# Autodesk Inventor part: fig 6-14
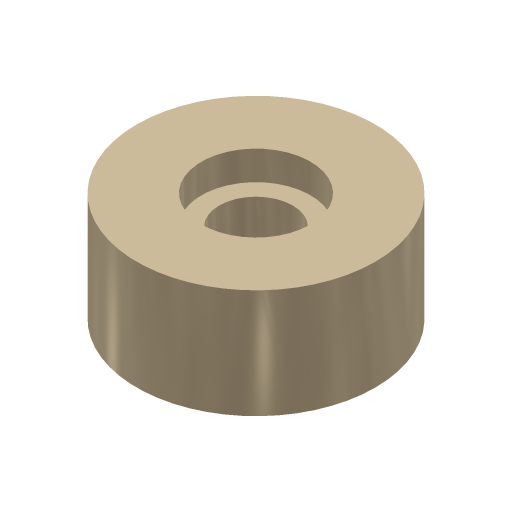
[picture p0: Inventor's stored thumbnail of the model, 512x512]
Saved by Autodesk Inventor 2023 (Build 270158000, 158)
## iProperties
Created: 2001-11
Part Number: fig 6-14
Document SubType Name: Modeling
Designer: Renu Muthoo
Density: 1 g/cm^3
Material: Generic
Appearance: Metal-Titanium (Polished)
Control State: 0
Master: False
Checked Out: False
Shininess: 65.0
Angle Display Precision: 2
Document Length Units: 11269
Document Angle Units: 11279
Document Time Units: 11290
Document Mass Units: 11283
Document Length Units Precision: 3
Document Angle Units Precision: 2
Density: 0.0
Volumn: 0.0
Area: 0.0
PropertySet Name: Model Information
Author: Renu Muthoo
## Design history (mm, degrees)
sketch "Sketch1"
  geometry: C1 r 16.401 at (0, 0)
  constraints: 1 centre point
extrude "Extrusion1" new body sketch "Sketch1" distance "d0" = 15; taper "d1" = 0 deg
hole "Hole3" diameter "d18" = 10.106; stored, may be unused: countersink angle "d22" = 90 deg, drill point angle "d24" = 118 deg; dims "d16" = 10, "d17" = 10, "d19" = 6, "d20" = 15, "d21" = 4, "d23" = 10
body "Solid1"
